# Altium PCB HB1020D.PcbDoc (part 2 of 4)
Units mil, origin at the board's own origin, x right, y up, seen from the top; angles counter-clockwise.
Board outline 4729.44 x 3075.9 mil, 2 copper layers (Top Layer, Bottom Layer); 113 components, 129 nets, 454 pads, 503 vias.
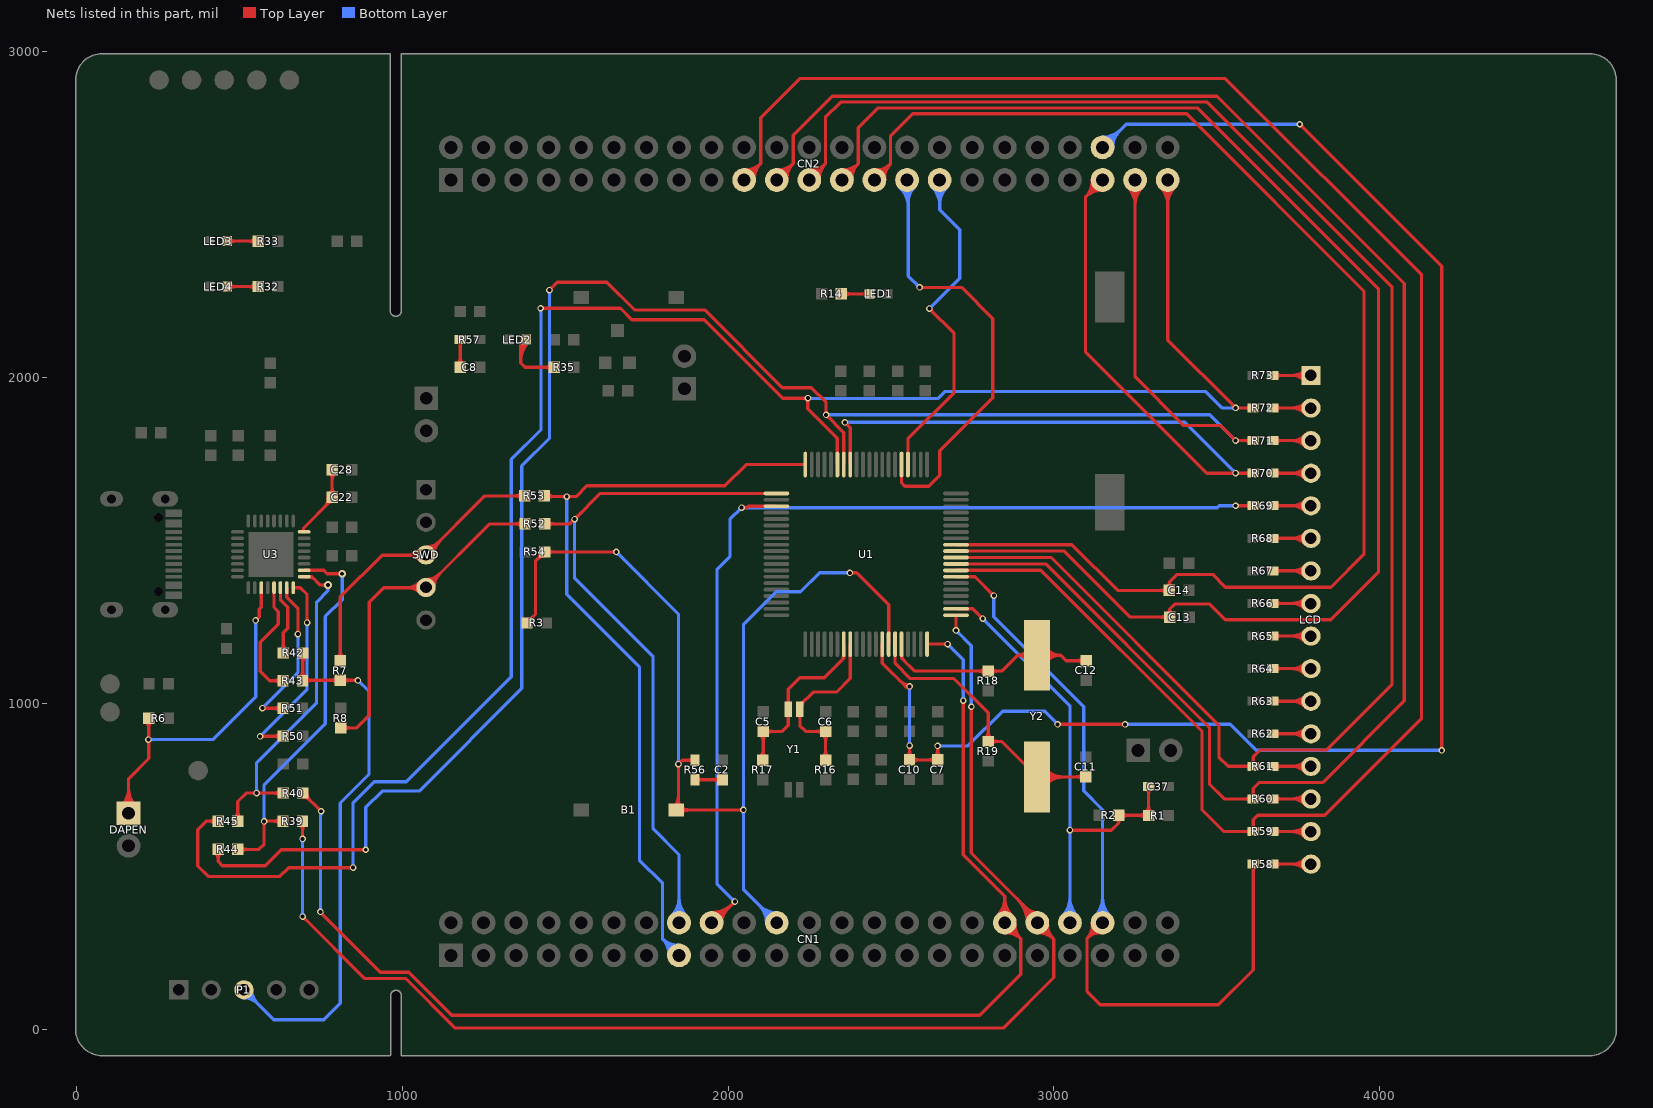
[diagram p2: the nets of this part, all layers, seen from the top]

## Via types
v1: diameter 20, hole 12, Top Layer to Bottom Layer, tented both sides, 475 vias
v2: diameter 23.62, hole 11.81, Top Layer to Bottom Layer, tented both sides, 20 vias
v3: diameter 122.05, hole 122.05, Top Layer to Bottom Layer, tented both sides, 4 vias
v4: diameter 39.37, hole 23.62, Top Layer to Bottom Layer, tented both sides, 2 vias
v5: diameter 30, hole 20, Top Layer to Bottom Layer, tented both sides, 1 vias
v6: diameter 15, hole 8, Top Layer to Bottom Layer, tented both sides, 1 vias

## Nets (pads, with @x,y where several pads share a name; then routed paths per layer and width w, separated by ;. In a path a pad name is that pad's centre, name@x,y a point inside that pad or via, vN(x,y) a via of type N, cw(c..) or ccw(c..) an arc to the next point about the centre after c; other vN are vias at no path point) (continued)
LINK_SWDIO: P1.3 R7.1 R42.2 R43.2 | length 2074.2
  Top Layer w10: R43.2@685.16,1078.84 ccw(c661.41,1102.59) 695,1102.59 ; R42.2@686.16,1146.16 cw(c664.82,1124.82) 695,1124.82 cw(c725.18,1124.82) R42.2@703.84,1146.16 ; R43.2@694,1070 R43.2@695,1071 ; 695,1097.76 ccw(c721.76,1097.76) 702.84,1078.84 ccw(c721.76,1097.76) 721.76,1071 ; R42.2@695,1155 R43.2@695,1071 ; R43.2@702.84,1061.16 cw(c726.59,1037.4) 726.59,1071 ; R7.1@801.16,1062.16 ccw(c779.82,1040.82) 779.82,1071 ccw(c779.83,1101.18) R7.1@801.16,1079.84 ; R7.1@818.84,1062.16 cw(c840.18,1040.82) 840.18,1071 cw(c840.18,1101.18) R7.1@818.84,1079.84 ; v1@860.46,1067.46 ccw(c851.93,1058.93) 851.93,1071 ccw(c851.93,1083.07) v1@860.46,1074.53 ; v1(864,1071) R7.1@810,1071 R43.2@695,1071
  Bottom Layer w10: P1.3@514,96.47 cw(c514,37.26) 555.87,79.13 cw(c597.74,121) P1.3@538.53,121 ; P1.3@514,106.47 cw(c514,71.4) 538.8,96.2 cw(c563.6,121) P1.3@528.53,121 ; P1.3@514,121 606,29 759,29 809.46,79.46 809.46,694.46 898,783 898,1037 v1(864,1071) ; v1@864,1066 cw(c864,1053.93) 872.54,1062.46 cw(c881.07,1071) v1@869,1071
LINK_USART_RX: R39.1 R44.1 U3.26 | length 1393
  Top Layer w10: R44.1@495,552 560,552 576,568 v1(576,638) 577,639 R39.1@634,639 ; R44.1@503.84,543.16 cw(c525.18,521.82) 525.18,552 cw(c525.18,582.18) R44.1@503.84,560.84 ; v1@572.46,634.46 cw(c563.93,625.93) 576,625.93 cw(c588.07,625.93) 579.54,634.46 cw(c590.49,623.51) 590.49,639 ; R39.1@625.16,630.16 ccw(c603.82,608.82) 603.82,639 ccw(c603.82,669.18) R39.1@625.16,647.84 ; U3.26@698.97,1408.57 758.82,1408.57 769.09,1398.31 v2(815.61,1398.31) ; v2@810.79,1393.49 ccw(c799.16,1381.86) 799.16,1398.31 ccw(c799.16,1414.75) v2@810.79,1403.12
  Bottom Layer w10: v1@572.46,641.54 ccw(c563.93,650.07) 576,650.07 ccw(c588.07,650.07) v1@579.54,641.54 ; v1(576,638) 576,750 764.06,938.06 764.06,1267.06 815.61,1318.61 v2(815.61,1398.31) ; v2@810.79,1393.49 cw(c799.16,1381.86) 815.61,1381.86 cw(c832.05,1381.86) v2@820.42,1393.49
LINK_USART_TX: R40.1 R45.1 U3.25 | length 1264.5
  Top Layer w10: R45.1@486.16,647.84 ccw(c464.82,669.18) 495,669.18 ccw(c525.18,669.18) R45.1@503.84,647.84 ; R45.1@495,639 495,699 521,725 v1(553,725) R40.1@635,725 ; v1@549.46,721.46 ccw(c540.93,712.93) 540.93,725 ccw(c540.93,737.07) v1@549.46,728.54 ; v1@556.54,721.46 cw(c565.07,712.93) 565.07,725 cw(c565.07,737.07) v1@556.54,728.54 ; R40.1@626.16,716.16 ccw(c604.82,694.82) 604.82,725 ccw(c604.82,755.18) R40.1@626.16,733.84 ; U3.25@697,1388.89 U3.25@698.97,1388.89 723.02,1388.89 748.61,1363.31 v2(772,1363.31) ; U3.25@713.14,1388.38 cw(c713.14,1363.28) 730.89,1381.03 ; U3.25@713.24,1388.39 cw(c716.47,1372.45) 727.97,1383.95 ; v2@767.18,1358.49 ccw(c755.56,1346.86) 755.56,1363.31 ccw(c755.56,1379.75) v2@767.18,1368.12
  Bottom Layer w10: v1@549.46,728.54 ccw(c540.93,737.07) 553,737.07 ccw(c565.07,737.07) v1@556.54,728.54 ; v1(553,725) 553,818 737,1002 737,1311 772,1346 v2(772,1363.31) ; v2@767.18,1358.49 cw(c755.56,1346.86) 772,1346.86 cw(c788.44,1346.86) v2@776.82,1358.49
LXTAL_IN: C5.2 R17.2 U1.7 Y1.1 | length 753.9
  Top Layer w10: R17.2@2098.16,834.84 ccw(c2074.41,858.59) 2108,858.59 ; C5.2@2099.16,905.16 cw(c2077.82,883.82) 2108,883.82 cw(c2138.18,883.82) 2116.84,905.16 cw(c2138.18,883.82) 2138.18,914 cw(c2138.18,944.18) C5.2@2116.84,922.84 ; R17.2@2107,826 2108,827 C5.2@2108,914 ; C5.2@2107,913 C5.2@2108,914 ; 2108,853.77 ccw(c2134.77,853.77) R17.2@2115.84,834.84 ; Y1.1@2180.45,966.16 cw(c2168.83,954.53) 2185.27,954.53 cw(c2201.71,954.53) Y1.1@2190.08,966.16 ; Y1.1@2180.45,999.42 ccw(c2168.83,1011.04) 2185.27,1011.04 ccw(c2201.71,1011.04) Y1.1@2190.08,999.42 ; 2346.5,1129.5 ccw(c2327.27,1148.73) U1.7@2354.46,1148.73 ; U1.7@2355.37,1182.2 2355.76,1181.81 2355.76,1138.76 2295.5,1078.5 2220.5,1078.5 2185.27,1043.27 Y1.1@2185.27,982.79 2185.27,933.27 2166,914 C5.2@2108,914
LXTAL_OUT: C6.2 R16.2 U1.8 Y1.4 | length 724.9
  Top Layer w10: Y1.4@2215.88,966.16 cw(c2204.26,954.53) 2220.7,954.53 cw(c2237.14,954.53) Y1.4@2225.52,966.16 ; Y1.4@2220.7,1001.41 ccw(c2220.7,1017.61) Y1.4@2232.15,1006.15 ; Y1.4@2227.51,994.6 cw(c2244.2,994.6) Y1.4@2232.4,1006.4 ; R16.2@2290.77,834.84 ccw(c2269.43,856.17) 2299.61,856.17 ; C6.2@2290.77,922.84 cw(c2269.43,944.18) 2269.43,914 cw(c2269.43,883.82) 2290.77,905.16 cw(c2269.43,883.82) 2299.61,883.82 cw(c2329.78,883.82) C6.2@2308.44,905.16 ; R16.2@2299.61,826 C6.2@2299.61,914 2238,914 2220.7,931.3 Y1.4@2220.7,982.79 2220.7,994.7 2261,1035 2333,1035 2375.05,1077.05 U1.8@2375.05,1182.2 ; 2299.61,856.18 ccw(c2329.79,856.18) R16.2@2308.45,834.84
MCU_SWCLK: R8.2 R52.1 SWD.4 | length 1418.3
  Top Layer w10: R8.2@811,925 860,925 899,964 899,1311 943.21,1355.21 SWD.4@1072,1355.21 ; R8.2@819.84,916.16 cw(c841.18,894.82) 841.18,925 cw(c841.18,955.18) R8.2@819.84,933.84 ; 1011.88,1355.21 ccw(c1011.88,1417.12) SWD.4@1055.66,1373.34 ; 1015.69,1355.21 cw(c1015.69,1298.69) SWD.4@1055.66,1338.66 ; 1036.02,1355.21 ccw(c1036.02,1392.98) SWD.4@1062.73,1366.27 ; 1039.83,1355.21 cw(c1039.83,1322.83) SWD.4@1062.73,1345.73 ; SWD.4@1073,1356 1268,1551 R52.1@1377,1551 ; SWD.4@1073,1370.53 ccw(c1073,1405.6) 1097.8,1380.8 ccw(c1122.6,1356) SWD.4@1087.53,1356 ; SWD.4@1073,1380.53 ccw(c1073,1439.74) 1114.87,1397.87 ccw(c1156.74,1356) SWD.4@1097.53,1356 ; R52.1@1368.16,1542.16 ccw(c1346.82,1520.82) 1346.82,1551 ccw(c1346.82,1581.18) R52.1@1368.16,1559.84
MCU_SWDIO: R7.2 R53.1 SWD.3 | length 1280.1
  Top Layer w10: R7.2@801.16,1139.84 ccw(c779.82,1161.18) 810,1161.18 ccw(c840.18,1161.18) R7.2@818.84,1139.84 ; R7.2@810,1131 810,1327 938.21,1455.21 SWD.3@1072,1455.21 ; 1011.88,1455.21 ccw(c1011.88,1517.12) SWD.3@1055.66,1473.34 ; 1015.69,1455.21 cw(c1015.69,1398.69) SWD.3@1055.66,1438.66 ; 1036.02,1455.21 ccw(c1036.02,1492.98) SWD.3@1062.73,1466.27 ; 1039.83,1455.21 cw(c1039.83,1422.83) SWD.3@1062.73,1445.73 ; SWD.3@1073,1456 1254,1637 R53.1@1376,1637 ; SWD.3@1073,1470.53 ccw(c1073,1505.6) 1097.8,1480.8 ccw(c1122.6,1456) SWD.3@1087.53,1456 ; SWD.3@1073,1480.53 ccw(c1073,1539.74) 1114.87,1497.87 ccw(c1156.74,1456) SWD.3@1097.53,1456 ; R53.1@1367.16,1628.16 ccw(c1345.82,1606.82) 1345.82,1637 ccw(c1345.82,1667.18) R53.1@1367.16,1645.84
NetC2_1: C2.1 R56.2 | length 164.7
  Top Layer w10: R56.2@1899,766 C2.1@1983,766 ; R56.2@1905.21,759.79 cw(c1920.2,744.8) 1920.2,766 cw(c1920.2,787.19) R56.2@1905.21,772.21 ; C2.1@1974.16,757.16 ccw(c1952.82,735.82) 1952.82,766 ccw(c1952.82,796.18) C2.1@1974.16,774.84
NetC8_2: C8.2 R57.2 | length 165.7
  Top Layer w10: C8.2@1169.16,2040.84 ccw(c1147.82,2062.18) 1178,2062.18 ccw(c1208.18,2062.18) C8.2@1186.84,2040.84 ; R57.2@1171.79,2110.79 cw(c1156.8,2095.81) 1178,2095.81 cw(c1199.2,2095.81) R57.2@1184.21,2110.79 ; C8.2@1178,2032 R57.2@1178,2117
NetC11_1: C11.1 R19.1 U1.15 Y2.1 | length 1206.2
  Top Layer w10: U1.15@2512.85,1182.2 2512.85,1123.06 2559.61,1076.31 2693.69,1076.31 2798.61,971.39 R19.1@2798.61,883.31 ; R19.1@2789.77,892.15 ccw(c2768.43,913.48) 2798.61,913.48 ccw(c2828.78,913.48) 2807.45,892.15 ccw(c2828.79,913.49) 2828.79,883.31 ccw(c2828.78,853.13) R19.1@2807.45,874.47 ; R19.1@2797.69,883.31 2839.6,883.31 Y2.1@2948.61,774.3 3096.6,774.3 C11.1@3097.61,775.31 ; Y2.1@2965.84,757.07 cw(c3007.44,715.47) 3007.44,774.3 cw(c3007.44,833.13) Y2.1@2965.84,791.53 ; Y2.1@2972.91,750 cw(c3031.58,691.32) 3031.58,774.3 cw(c3031.58,857.28) Y2.1@2972.91,798.6 ; 3065,774.3 ccw(c3065,807.91) C11.1@3088.77,784.14 ; 3069.86,774.3 cw(c3069.86,747.56) C11.1@3088.77,766.47
NetC12_1: C12.1 R18.1 U1.16 Y2.2 | length 1114.1
  Top Layer w10: U1.16@2532.54,1182.2 2532.54,1139.38 2572.61,1099.31 R18.1@2798.61,1099.31 2840.61,1099.31 2889.61,1148.31 ; U1.16@2533.44,1148.73 ccw(c2558.21,1148.73) 2540.7,1131.22 ; R18.1@2789.77,1090.47 ccw(c2768.43,1069.13) 2768.43,1099.31 ccw(c2768.43,1129.49) R18.1@2789.77,1108.15 ; R18.1@2807.45,1090.47 cw(c2828.78,1069.13) 2828.78,1099.31 cw(c2828.79,1129.49) R18.1@2807.45,1108.15 ; Y2.2@2918.71,1131.36 ccw(c2889.61,1114.87) 2889.61,1148.31 ; Y2.2@2918.71,1165.26 cw(c2889.61,1181.76) 2889.61,1148.31 ; Y2.2@2927.41,1136.3 ccw(c2906.78,1124.6) 2906.78,1148.31 ccw(c2906.78,1172.03) Y2.2@2927.41,1160.33 ; Y2.2@2967.53,1132.95 cw(c2999.78,1106.77) 2999.78,1148.31 cw(c2999.78,1189.85) Y2.2@2967.53,1163.67 ; Y2.2@2975.29,1126.65 cw(c3020.78,1089.73) 3020.78,1148.31 ; Y2.2@2975.29,1169.98 ccw(c3020.78,1206.9) 3020.78,1148.31 ; C12.1@3090.77,1122.47 ccw(c3069.43,1101.13) 3069.43,1131.31 ccw(c3069.43,1161.49) C12.1@3090.77,1140.15 ; C12.1@3099.61,1131.31 3037.79,1131.31 3020.78,1148.31 ; 2889.61,1148.31 Y2.2@2948.61,1148.31 3020.78,1148.31
NetC22_2: C22.2 C28.2 U3.32 | length 369.8
  Top Layer w10: U3.32@697,1526.68 697,1538.18 781.11,1622.29 784.61,1625.79 C28.2@784.61,1711.79 ; 697,1532.67 ccw(c704.96,1532.67) U3.32@699.33,1527.05 ; 760.02,1601.21 ccw(c728.44,1632.79) C22.2@773.11,1632.79 ; C22.2@774.51,1615.69 cw(c785.61,1604.6) C22.2@785.61,1620.29 ; C22.2@776.77,1641.63 ccw(c757.84,1660.55) 784.61,1660.55 ; C28.2@776.77,1707.95 cw(c757.84,1689.03) 784.61,1689.03 ; 784.61,1665.38 ccw(c818.2,1665.38) C22.2@794.45,1641.63 ; 784.61,1684.2 cw(c818.2,1684.2) C28.2@794.45,1707.95
NetDAPEN_1: DAPEN.1 R6.1 U3.19 | length 1372.4
  Top Layer w10: DAPEN.1@137.78,685.22 ccw(c84.15,738.85) 160,738.85 ccw(c235.85,738.85) DAPEN.1@182.22,685.22 ; DAPEN.1@144.86,678.14 ccw(c108.29,714.71) 160,714.71 ccw(c211.71,714.71) DAPEN.1@175.14,678.14 ; DAPEN.1@160,663 160,769 222,831 R6.1@222,955 ; R6.1@213.16,946.16 cw(c191.82,924.82) 222,924.82 cw(c252.18,924.82) R6.1@230.84,946.16 ; v1@217.46,885.46 cw(c206.51,874.51) 222,874.51 ; v1@217.46,892.54 ccw(c206.51,903.49) 222,903.49 ; v1(550,1255) 561.19,1266.19 561.19,1289.28 567.08,1295.17 U3.19@567.08,1355.43 ; v1@550,1260 ccw(c550,1272.07) 558.54,1263.54 ccw(c567.07,1255) v1@555,1255
  Bottom Layer w10: v1(221,889) 419,889 550,1020 v1(550,1255) ; v1@224.54,885.46 cw(c233.07,876.93) 233.07,889 cw(c233.07,901.07) v1@224.54,892.54 ; v1@546.46,1251.46 cw(c537.93,1242.93) 550,1242.93 cw(c562.07,1242.93) v1@553.54,1251.46
NetLCD_1: LCD.1 R73.2 | length 298.6
  Top Layer w10: R73.2@3672,2007 LCD.1@3789.2,2007 ; R73.2@3681.93,2000.79 cw(c3696.92,1985.8) 3696.92,2007 cw(c3696.92,2028.2) R73.2@3681.93,2013.21 ; 3729.62,2007 cw(c3729.62,1946.9) LCD.1@3772.11,1989.4 ; 3730.87,2007 ccw(c3730.87,2065.33) LCD.1@3772.11,2024.08 ; 3753.76,2007 cw(c3753.76,1971.04) LCD.1@3779.18,1996.47 ; 3755.01,2007 ccw(c3755.01,2041.19) LCD.1@3779.18,2017.01
NetLCD_2: LCD.2 R72.2 | length 298.6
  Top Layer w10: R72.2@3672,1907 LCD.2@3789.2,1907 ; R72.2@3681.93,1900.79 cw(c3696.92,1885.8) 3696.92,1907 cw(c3696.92,1928.2) R72.2@3681.93,1913.21 ; 3729.62,1907 cw(c3729.62,1846.9) LCD.2@3772.11,1889.4 ; 3730.87,1907 ccw(c3730.87,1965.33) LCD.2@3772.11,1924.08 ; 3753.76,1907 cw(c3753.76,1871.04) LCD.2@3779.18,1896.47 ; 3755.01,1907 ccw(c3755.01,1941.19) LCD.2@3779.18,1917.01
NetLCD_3: LCD.3 R71.2 | length 298.6
  Top Layer w10: R71.2@3672,1807 LCD.3@3789.2,1807 ; R71.2@3681.93,1800.79 cw(c3696.92,1785.8) 3696.92,1807 cw(c3696.92,1828.2) R71.2@3681.93,1813.21 ; 3729.62,1807 cw(c3729.62,1746.9) LCD.3@3772.11,1789.4 ; 3730.87,1807 ccw(c3730.87,1865.33) LCD.3@3772.11,1824.08 ; 3753.76,1807 cw(c3753.76,1771.04) LCD.3@3779.18,1796.47 ; 3755.01,1807 ccw(c3755.01,1841.19) LCD.3@3779.18,1817.01
NetLCD_4: LCD.4 R70.2 | length 298.6
  Top Layer w10: R70.2@3672,1707 LCD.4@3789.2,1707 ; R70.2@3681.93,1700.79 cw(c3696.92,1685.8) 3696.92,1707 cw(c3696.92,1728.2) R70.2@3681.93,1713.21 ; 3729.62,1707 cw(c3729.62,1646.9) LCD.4@3772.11,1689.4 ; 3730.87,1707 ccw(c3730.87,1765.33) LCD.4@3772.11,1724.08 ; 3753.76,1707 cw(c3753.76,1671.04) LCD.4@3779.18,1696.47 ; 3755.01,1707 ccw(c3755.01,1741.19) LCD.4@3779.18,1717.01
NetLCD_5: LCD.5 R69.2 | length 298.6
  Top Layer w10: R69.2@3672,1607 LCD.5@3789.2,1607 ; R69.2@3681.93,1600.79 cw(c3696.92,1585.8) 3696.92,1607 cw(c3696.92,1628.2) R69.2@3681.93,1613.21 ; 3729.62,1607 cw(c3729.62,1546.9) LCD.5@3772.11,1589.4 ; 3730.87,1607 ccw(c3730.87,1665.33) LCD.5@3772.11,1624.08 ; 3753.76,1607 cw(c3753.76,1571.04) LCD.5@3779.18,1596.47 ; 3755.01,1607 ccw(c3755.01,1641.19) LCD.5@3779.18,1617.01
NetLCD_6: LCD.6 R68.2 | length 298.6
  Top Layer w10: R68.2@3672,1507 LCD.6@3789.2,1507 ; R68.2@3681.93,1500.79 cw(c3696.92,1485.8) 3696.92,1507 cw(c3696.92,1528.2) R68.2@3681.93,1513.21 ; 3729.62,1507 cw(c3729.62,1446.9) LCD.6@3772.11,1489.4 ; 3730.87,1507 ccw(c3730.87,1565.33) LCD.6@3772.11,1524.08 ; 3753.76,1507 cw(c3753.76,1471.04) LCD.6@3779.18,1496.47 ; 3755.01,1507 ccw(c3755.01,1541.19) LCD.6@3779.18,1517.01
NetLCD_7: LCD.7 R67.2 | length 298.6
  Top Layer w10: R67.2@3672,1407 LCD.7@3789.2,1407 ; R67.2@3681.93,1400.79 cw(c3696.92,1385.8) 3696.92,1407 cw(c3696.92,1428.2) R67.2@3681.93,1413.21 ; 3729.62,1407 cw(c3729.62,1346.9) LCD.7@3772.11,1389.4 ; 3730.87,1407 ccw(c3730.87,1465.33) LCD.7@3772.11,1424.08 ; 3753.76,1407 cw(c3753.76,1371.04) LCD.7@3779.18,1396.47 ; 3755.01,1407 ccw(c3755.01,1441.19) LCD.7@3779.18,1417.01
NetLCD_8: LCD.8 R66.2 | length 298.6
  Top Layer w10: R66.2@3672,1307 LCD.8@3789.2,1307 ; R66.2@3681.93,1300.79 cw(c3696.92,1285.8) 3696.92,1307 cw(c3696.92,1328.2) R66.2@3681.93,1313.21 ; 3729.62,1307 cw(c3729.62,1246.9) LCD.8@3772.11,1289.4 ; 3730.87,1307 ccw(c3730.87,1365.33) LCD.8@3772.11,1324.08 ; 3753.76,1307 cw(c3753.76,1271.04) LCD.8@3779.18,1296.47 ; 3755.01,1307 ccw(c3755.01,1341.19) LCD.8@3779.18,1317.01
NetLCD_9: LCD.9 R65.2 | length 298.6
  Top Layer w10: R65.2@3672,1207 LCD.9@3789.2,1207 ; R65.2@3681.93,1200.79 cw(c3696.92,1185.8) 3696.92,1207 cw(c3696.92,1228.2) R65.2@3681.93,1213.21 ; 3729.62,1207 cw(c3729.62,1146.9) LCD.9@3772.11,1189.4 ; 3730.87,1207 ccw(c3730.87,1265.33) LCD.9@3772.11,1224.08 ; 3753.76,1207 cw(c3753.76,1171.04) LCD.9@3779.18,1196.47 ; 3755.01,1207 ccw(c3755.01,1241.19) LCD.9@3779.18,1217.01
NetLCD_10: LCD.10 R64.2 | length 298.6
  Top Layer w10: R64.2@3672,1107 LCD.10@3789.2,1107 ; R64.2@3681.93,1100.79 cw(c3696.92,1085.8) 3696.92,1107 cw(c3696.92,1128.2) R64.2@3681.93,1113.21 ; 3729.62,1107 cw(c3729.62,1046.9) LCD.10@3772.11,1089.4 ; 3730.87,1107 ccw(c3730.87,1165.33) LCD.10@3772.11,1124.08 ; 3753.76,1107 cw(c3753.76,1071.04) LCD.10@3779.18,1096.47 ; 3755.01,1107 ccw(c3755.01,1141.19) LCD.10@3779.18,1117.01
NetLCD_11: LCD.11 R63.2 | length 298.6
  Top Layer w10: R63.2@3672,1007 LCD.11@3789.2,1007 ; R63.2@3681.93,1000.79 cw(c3696.92,985.8) 3696.92,1007 cw(c3696.92,1028.2) R63.2@3681.93,1013.21 ; 3729.62,1007 cw(c3729.62,946.9) LCD.11@3772.11,989.4 ; 3730.87,1007 ccw(c3730.87,1065.33) LCD.11@3772.11,1024.08 ; 3753.76,1007 cw(c3753.76,971.04) LCD.11@3779.18,996.47 ; 3755.01,1007 ccw(c3755.01,1041.19) LCD.11@3779.18,1017.01
NetLCD_12: LCD.12 R62.2 | length 298.6
  Top Layer w10: R62.2@3672,907 LCD.12@3789.2,907 ; R62.2@3681.93,900.79 cw(c3696.92,885.8) 3696.92,907 cw(c3696.92,928.2) R62.2@3681.93,913.21 ; 3729.62,907 cw(c3729.62,846.9) LCD.12@3772.11,889.4 ; 3730.87,907 ccw(c3730.87,965.33) LCD.12@3772.11,924.08 ; 3753.76,907 cw(c3753.76,871.04) LCD.12@3779.18,896.47 ; 3755.01,907 ccw(c3755.01,941.19) LCD.12@3779.18,917.01
NetLCD_13: LCD.13 R61.2 | length 298.6
  Top Layer w10: R61.2@3672,807 LCD.13@3789.2,807 ; R61.2@3681.93,800.79 cw(c3696.92,785.8) 3696.92,807 cw(c3696.92,828.2) R61.2@3681.93,813.21 ; 3729.62,807 cw(c3729.62,746.9) LCD.13@3772.11,789.4 ; 3730.87,807 ccw(c3730.87,865.33) LCD.13@3772.11,824.08 ; 3753.76,807 cw(c3753.76,771.04) LCD.13@3779.18,796.47 ; 3755.01,807 ccw(c3755.01,841.19) LCD.13@3779.18,817.01
NetLCD_14: LCD.14 R60.2 | length 298.6
  Top Layer w10: R60.2@3672,707 LCD.14@3789.2,707 ; R60.2@3681.93,700.79 cw(c3696.92,685.8) 3696.92,707 cw(c3696.92,728.2) R60.2@3681.93,713.21 ; 3729.62,707 cw(c3729.62,646.9) LCD.14@3772.11,689.4 ; 3730.87,707 ccw(c3730.87,765.33) LCD.14@3772.11,724.08 ; 3753.76,707 cw(c3753.76,671.04) LCD.14@3779.18,696.47 ; 3755.01,707 ccw(c3755.01,741.19) LCD.14@3779.18,717.01
NetLCD_15: LCD.15 R59.2 | length 298.6
  Top Layer w10: R59.2@3672,607 LCD.15@3789.2,607 ; R59.2@3681.93,600.79 cw(c3696.92,585.8) 3696.92,607 cw(c3696.92,628.2) R59.2@3681.93,613.21 ; 3729.62,607 cw(c3729.62,546.9) LCD.15@3772.11,589.4 ; 3730.87,607 ccw(c3730.87,665.33) LCD.15@3772.11,624.08 ; 3753.76,607 cw(c3753.76,571.04) LCD.15@3779.18,596.47 ; 3755.01,607 ccw(c3755.01,641.19) LCD.15@3779.18,617.01
NetLCD_16: LCD.16 R58.2 | length 298.6
  Top Layer w10: R58.2@3672,507 LCD.16@3789.2,507 ; R58.2@3681.93,500.79 cw(c3696.92,485.8) 3696.92,507 cw(c3696.92,528.2) R58.2@3681.93,513.21 ; 3729.62,507 cw(c3729.62,446.9) LCD.16@3772.11,489.4 ; 3730.87,507 ccw(c3730.87,565.33) LCD.16@3772.11,524.08 ; 3753.76,507 cw(c3753.76,471.04) LCD.16@3779.18,496.47 ; 3755.01,507 ccw(c3755.01,541.19) LCD.16@3779.18,517.01
NetLED1_1: LED1.1 R14.1 | length 172.3
  Top Layer w10: R14.1@2348,2257 LED1.1@2435,2257 ; R14.1@2356.84,2248.16 cw(c2378.18,2226.82) 2378.18,2257 cw(c2378.18,2287.18) R14.1@2356.84,2265.84 ; LED1.1@2427.93,2249.93 ccw(c2410.86,2232.86) 2410.86,2257 ccw(c2410.86,2281.14) LED1.1@2427.93,2264.07
NetLED2_1: LED2.1 R35.1 | length 409.2
  Top Layer w10: 1364.01,2051.84 cw(c1446.16,2051.84) LED2.1@1388.07,2109.93 ; 1364.01,2075.98 cw(c1422.02,2075.98) LED2.1@1381,2117 1364.01,2100.01 ; 1364.01,2100.12 cw(c1397.88,2100.12) LED2.1@1373.93,2124.07 ; LED2.1@1371,2116.97 cw(c1347.13,2116.89) 1364.01,2100.01 ; LED2.1@1380.97,2107 ccw(c1380.89,2083.13) 1364.01,2100.01 ; R35.1@1458.16,2023.16 ccw(c1436.82,2001.82) 1436.82,2032 ccw(c1436.82,2062.18) R35.1@1458.16,2040.84 ; R35.1@1467,2032 1377,2032 1364.01,2044.99 1364.01,2100.01
NetLED3_2: LED3.2 R33.2 | length 181.3
  Top Layer w10: LED3.2@462.61,2419.31 R33.2@558.61,2419.31 ; LED3.2@469.68,2412.24 cw(c486.75,2395.17) 486.75,2419.31 cw(c486.75,2443.45) LED3.2@469.68,2426.38 ; R33.2@549.77,2410.47 ccw(c528.43,2389.13) 528.43,2419.31 ccw(c528.43,2449.49) R33.2@549.77,2428.15
NetLED4_2: LED4.2 R32.2 | length 181.3
  Top Layer w10: LED4.2@462.61,2279.79 R32.2@558.61,2279.79 ; LED4.2@469.68,2272.72 cw(c486.75,2255.65) 486.75,2279.79 cw(c486.75,2303.93) LED4.2@469.68,2286.86 ; R32.2@549.77,2270.95 ccw(c528.43,2249.61) 528.43,2279.79 ccw(c528.43,2309.97) R32.2@549.77,2288.63
NetR42_1: R42.1 U3.22 | length 264.7
  Top Layer w10: U3.22@626.13,1357.39 U3.22@626.13,1355.43 626.13,1318.26 648.61,1295.79 648.61,1230.61 635,1217 R42.1@635,1155 ; R42.1@626.16,1163.84 ccw(c604.82,1185.18) 635,1185.18 ccw(c665.18,1185.18) R42.1@643.84,1163.84
NetR43_1: R43.1 U3.21 | length 416.3
  Top Layer w10: U3.21@606.45,1357.39 U3.21@606.45,1355.43 606.45,1295.03 619.61,1281.88 619.61,1243.61 564,1188 564,1099 593,1070 R43.1@634,1070 ; R43.1@625.16,1061.16 ccw(c603.82,1039.82) 603.82,1070 ccw(c603.82,1100.18) R43.1@625.16,1078.84
NetR50_1: R50.1 U3.24 | length 739.5
  Top Layer w10: v1(564,899) R50.1@634,899 ; v1@567.54,895.46 cw(c576.07,886.93) 576.07,899 cw(c576.07,911.07) v1@567.54,902.54 ; 602.41,899 ccw(c602.41,932.59) R50.1@626.16,908.84 ; 607.24,899 cw(c607.24,872.24) R50.1@626.16,891.16 ; U3.24@665.5,1355.43 686.97,1355.43 708,1334.39 v1(708,1248) ; v1@704.46,1251.54 ccw(c695.93,1260.07) 708,1260.07 ccw(c720.07,1260.07) v1@711.54,1251.54
  Bottom Layer w10: v1(564,899) 708,1043 v1(708,1248) ; v1@564,904 ccw(c564,916.07) 572.54,907.54 ccw(c581.07,899) v1@569,899 ; v1@704.46,1244.46 cw(c695.93,1235.93) 708,1235.93 cw(c720.07,1235.93) v1@711.54,1244.46
NetR51_1: R51.1 U3.23 | length 615.6
  Top Layer w10: v1@571,985 R51.1@634,985 ; v1@574.04,981.96 cw(c581.36,974.64) 581.36,985 ; v1@574.04,989.04 ccw(c583.78,998.78) 583.78,985 ; R51.1@625.16,976.16 ccw(c603.82,954.82) 603.82,985 ccw(c603.82,1015.18) R51.1@625.16,993.84 ; U3.23@645.82,1355.43 645.82,1326.57 679.88,1292.51 v1(679.88,1213.12) ; v1@676.35,1216.65 ccw(c667.81,1225.19) 679.88,1225.19 ccw(c691.95,1225.19) v1@683.42,1216.65
  Bottom Layer w10: v1(570.5,985.5) 679.88,1094.88 v1(679.88,1213.12) ; v1@570.5,990.5 ccw(c570.5,1002.57) 579.04,994.04 ccw(c587.57,985.5) v1@575.5,985.5 ; v1@676.35,1209.58 cw(c667.81,1201.05) 679.88,1201.05 cw(c691.95,1201.05) v1@683.42,1209.58
NRST: B1.2 CN1.22 R3.2 R54.2 R56.1 U1.14 | length 3906.1
  Top Layer w10: R3.2@1383,1247 1409,1273 1409,1437 R54.2@1437,1465 v1(1657,1465) ; R3.2@1383,1259.5 ccw(c1383,1289.68) 1404.34,1268.34 ccw(c1425.68,1247) R3.2@1395.5,1247 ; R54.2@1424.5,1465 cw(c1394.32,1465) 1415.66,1443.66 cw(c1437,1422.32) R54.2@1437,1452.5 ; R54.2@1445.84,1456.16 cw(c1467.18,1434.82) 1467.18,1465 cw(c1467.18,1495.18) R54.2@1445.84,1473.84 ; v1@1653.46,1461.46 ccw(c1644.93,1452.93) 1644.93,1465 ccw(c1644.93,1477.07) v1@1653.46,1468.54 ; B1.2@1834.5,683.38 ccw(c1801.9,715.98) 1848,715.98 ; v1@1844.46,810.46 cw(c1835.93,801.93) 1848,801.93 cw(c1860.07,801.93) v1@1851.54,810.46 ; 1848,700.93 ccw(c1872.81,700.93) 1855.27,683.38 ccw(c1880.34,708.45) 1880.34,673 ccw(c1880.34,637.55) B1.2@1855.27,662.62 ; v1@1848,819 ccw(c1848,831.07) 1856.54,822.54 ccw(c1865.07,814) v1@1853,814 ; R56.1@1892.79,819.79 ccw(c1877.8,804.8) 1877.8,826 ccw(c1877.8,847.19) R56.1@1892.79,832.21 ; R56.1@1899,826 1860,826 v1(1848,814) 1848,680.05 B1.2@1840.95,673 v1(2047.3,673) ; v1@2043.76,669.46 ccw(c2035.23,660.93) 2035.23,673 ccw(c2035.23,685.07) v1@2043.76,676.54 ; v1(2374,1401) 2394.53,1401 2493.17,1302.36 U1.14@2493.17,1182.2 ; v1@2377.54,1397.46 cw(c2386.07,1388.93) 2386.07,1401 cw(c2386.07,1413.07) v1@2377.54,1404.54
  Bottom Layer w10: v1@1657,1460 cw(c1657,1447.93) 1665.54,1456.46 cw(c1674.07,1465) v1@1662,1465 ; v1(1657,1465) 1848,1274 v1(1848,814) ; v1@1844.46,817.54 ccw(c1835.93,826.07) 1848,826.07 ccw(c1860.07,826.07) v1@1851.54,817.54 ; v1@2043.76,669.46 cw(c2035.23,660.93) 2047.3,660.93 cw(c2059.37,660.93) v1@2050.83,669.46 ; v1@2043.76,676.54 ccw(c2035.23,685.07) 2047.3,685.07 ccw(c2059.37,685.07) v1@2050.83,676.54 ; CN1.22@2118.19,326.79 ccw(c2042.34,326.79) 2095.97,380.42 ccw(c2149.61,434.05) CN1.22@2149.61,358.21 ; CN1.22@2128.19,326.79 ccw(c2076.48,326.79) 2113.04,363.35 ccw(c2149.61,399.91) CN1.22@2149.61,348.21 ; CN1.22@2148.61,324.62 CN1.22@2148.61,326.79 ; CN1.22@2149.61,326.79 2047.3,429.1 2047.3,1242.08 2147.79,1342.57 2222.57,1342.57 2281,1401 v1(2374,1401) ; v1@2370.46,1397.46 ccw(c2361.93,1388.93) 2361.93,1401 ccw(c2361.93,1413.07) v1@2370.46,1404.54
PA0: C7.2 C10.2 CN2.42 U1.13 | length 5608.1
  Top Layer w10: U1.13@2473.48,1182.2 2473.48,1123.52 2545,1052 ; 2527.33,1069.67 ccw(c2557.27,1099.61) v1@2557.27,1057.27 ; 2544.4,1052.6 ccw(c2557.27,1065.47) v1@2557.27,1047.27 ; 2545.85,1052 cw(c2545.85,1040.85) v1@2553.73,1048.73 ; C10.2@2548.43,835.62 ccw(c2527.09,856.96) 2557.27,856.96 ccw(c2587.45,856.96) 2566.11,835.62 ccw(c2587.45,856.96) 2587.45,826.79 ccw(c2587.45,796.61) C10.2@2566.11,817.95 ; v1@2553.64,1055.71 cw(c2545,1063.92) 2545,1052 ; v1@2553.73,867.19 cw(c2545.2,858.66) 2557.27,858.66 cw(c2569.34,858.66) v1@2560.81,867.19 ; v1(2557.27,870.73) C10.2@2557.27,826.79 C7.2@2643.61,826.79 v1(2643.61,869.61) ; v1(2557.27,1052.27) 2557.27,1052.05 2557.22,1052 2545,1052 ; C7.2@2634.77,817.95 ccw(c2613.43,796.61) 2613.43,826.79 ccw(c2613.43,856.96) 2634.77,835.62 ccw(c2613.43,856.96) 2643.61,856.96 ccw(c2673.79,856.97) C7.2@2652.45,835.62 ; v1@2640.07,866.07 cw(c2631.53,857.53) 2643.61,857.53 cw(c2655.68,857.53) v1@2647.14,866.07 ; v1(3012,936) v1(3219,936) ; v1@3015.54,932.46 cw(c3024.07,923.93) 3024.07,936 cw(c3024.07,948.07) v1@3015.54,939.54 ; v1@3215.46,932.46 ccw(c3206.93,923.93) 3206.93,936 ccw(c3206.93,948.07) v1@3215.46,939.54 ; v1@3755,2773 cw(c3755,2760.93) 3763.54,2769.46 cw(c3772.07,2778) v1@3760,2778 ; v1(3755,2778) 4191,2342 v1(4191,856) ; v1@4187.46,859.54 ccw(c4178.93,868.07) 4191,868.07 ccw(c4203.07,868.07) v1@4194.54,859.54
  Bottom Layer w10: v1@2553.73,874.27 ccw(c2545.2,882.8) 2557.27,882.8 ccw(c2569.34,882.8) v1@2560.81,874.27 ; v1@2553.73,1048.73 cw(c2545.2,1040.2) 2557.27,1040.2 cw(c2569.34,1040.2) v1@2560.81,1048.73 ; v1(2557.27,870.73) v1(2557.27,1052.27) ; v1(2643.61,869.61) 2736.61,869.61 2843,976 2972,976 v1(3012,936) ; v1@2647.14,866.07 cw(c2655.68,857.53) 2655.68,869.61 cw(c2655.68,881.68) v1@2647.14,873.14 ; v1@3007,936 ccw(c2994.93,936) 3003.46,944.54 ccw(c3012,953.07) v1@3012,941 ; CN2.42@3149.61,2706.79 3150.77,2706.79 3221.98,2778 v1(3755,2778) ; CN2.42@3149.61,2728.21 ccw(c3149.61,2782.73) 3188.16,2744.17 ; CN2.42@3149.61,2738.21 ccw(c3149.61,2816.87) 3205.23,2761.25 ; CN2.42@3171.02,2706.79 cw(c3219.91,2706.79) 3185.34,2741.36 ; CN2.42@3181.02,2706.79 cw(c3254.06,2706.79) 3202.41,2758.43 ; v1(3219,936) 3541,936 3621,856 v1(4191,856) ; v1@3222.54,932.46 cw(c3231.07,923.93) 3231.07,936 cw(c3231.07,948.07) v1@3222.54,939.54 ; v1@3751.46,2774.46 ccw(c3742.93,2765.93) 3742.93,2778 ccw(c3742.93,2790.07) v1@3751.46,2781.54 ; v1@4187.46,852.46 ccw(c4178.93,843.93) 4178.93,856 ccw(c4178.93,868.07) v1@4187.46,859.54
PA1: CN1.36 R40.2 U1.20 | length 4450.9
  Top Layer w10: R40.2@695,712.5 cw(c695,682.32) 716.34,703.66 cw(c737.68,725) R40.2@707.5,725 ; R40.2@695,725 v1(751,669) ; v1@746,669 ccw(c733.93,669) 742.46,677.53 ccw(c751,686.07) v1@751,674 ; v1@751,356 932,175 1020,175 1152,43 2773,43 2899,169 2899,277.39 ; v1@753.99,360 ccw(c770.86,360) 758.93,348.07 ; U1.20@2611.28,1182.2 v1(2674,1182.2) ; v1@2670.46,1178.66 ccw(c2661.93,1170.12) 2661.93,1182.2 ccw(c2661.93,1194.27) v1@2670.46,1185.73 ; v1@2718.46,1005.46 cw(c2709.93,996.93) 2722,996.93 cw(c2734.07,996.93) v1@2725.54,1005.46 ; v1(2722,1009) 2722,535.65 2849.61,408.04 CN1.36@2849.61,326.79 2899,277.39 ; CN1.36@2827.39,349 ccw(c2773.76,402.64) 2849.61,402.64 ccw(c2925.45,402.64) CN1.36@2871.82,349 ; CN1.36@2834.46,341.93 ccw(c2797.9,378.49) 2849.61,378.49 ccw(c2901.31,378.49) CN1.36@2864.75,341.93 ; CN1.36@2850.89,305.41 cw(c2853.42,263.26) 2883.28,293.12 cw(c2913.13,322.97) CN1.36@2870.99,325.5 ; CN1.36@2851.49,295.43 cw(c2855.2,233.6) 2899,277.4 ; CN1.36@2880.97,324.91 ccw(c2942.8,321.19) 2899,277.4
  Bottom Layer w10: v1@745.45,363.54 ccw(c736.92,372.07) 748.99,372.07 ccw(c761.06,372.07) v1@752.52,363.54 ; v1(748.99,360) v1@748.99,666.99 ; 748.99,652.07 cw(c767.93,652.07) v1@754.54,665.46 ; v1@2674,1177.2 cw(c2674,1165.12) 2682.54,1173.66 cw(c2691.07,1182.2) v1@2679,1182.2 ; v1(2674,1182.2) 2722,1134.2 v1(2722,1009) ; v1@2718.46,1012.54 ccw(c2709.93,1021.07) 2722,1021.07 ccw(c2734.07,1021.07) v1@2725.54,1012.54
PA2: CN1.38 R39.2 U1.21 | length 4647.8
  Top Layer w10: R39.2@685.16,630.16 cw(c663.82,608.82) 694,608.82 cw(c724.18,608.82) R39.2@702.84,630.16 ; v1@690.46,587.54 ccw(c681.93,596.07) 694,596.07 ccw(c706.07,596.07) v1@697.53,587.54 ; v1@694,341 cw(c694,328.93) 702.53,337.47 cw(c711.07,346) v1@699,346 ; v1(694,346) 884,156 1010,156 1162.39,3.61 2844.77,3.61 3000,158.84 3000,276.39 ; v1(694,584) R39.2@694,639 ; v1@2696.32,1227.68 ccw(c2687.79,1236.21) 2699.86,1236.21 ccw(c2711.93,1236.21) v1@2703.39,1227.68 ; v1(2699.86,1224.14) U1.21@2699.86,1270.78 ; v1@2743.46,986.46 cw(c2734.93,977.93) 2747,977.93 cw(c2759.07,977.93) v1@2750.54,986.46 ; v1(2747,990) 2747,541 2949.61,338.39 CN1.38@2949.61,326.79 3000,276.39 ; 2887.77,400.23 cw(c2814.32,326.79) CN1.38@2918.19,326.79 ; 2904.84,383.16 cw(c2848.46,326.79) CN1.38@2928.19,326.79 ; 2915.79,372.21 ccw(c2949.61,406.03) CN1.38@2949.61,358.21 ; 2921.91,366.09 cw(c2882.61,326.79) CN1.38@2938.19,326.79 ; CN1.38@2950.57,305.39 cw(c2952.57,261.05) 2983.96,292.44 cw(c3015.35,323.82) CN1.38@2971,325.82 ; CN1.38@2951.02,295.4 cw(c2953.95,230.35) 3000,276.4 ; CN1.38@2980.99,325.37 ccw(c3046.04,322.44) 3000,276.4
  Bottom Layer w10: v1@690.46,349.54 ccw(c681.93,358.07) 694,358.07 ccw(c706.07,358.07) v1@697.53,349.54 ; v1@690.46,580.47 cw(c681.93,571.93) 694,571.93 cw(c706.07,571.93) v1@697.53,580.47 ; v1(694,346) v1(694,584) ; v1@2699.86,1219.14 cw(c2699.86,1207.07) 2708.39,1215.61 cw(c2716.93,1224.14) v1@2704.86,1224.14 ; v1(2699.86,1224.14) 2747,1177 v1(2747,990) ; v1@2743.46,993.54 ccw(c2734.93,1002.07) 2747,1002.07 ccw(c2759.07,1002.07) v1@2750.54,993.54
PA3: C37.1 CN1.40 R1.1 R2.2 U1.22 | length 2005.8
  Top Layer w10: U1.22@2699.86,1290.46 2751.73,1290.46 v1(2782,1260.2) ; v1@2777,1260.2 ccw(c2764.93,1260.2) 2773.46,1268.73 ccw(c2782,1277.27) v1@2782,1265.2 ; v1(3049.61,611) 3177,611 3199,633 ; v1@3053.14,607.46 cw(c3061.68,598.93) 3061.68,611 cw(c3061.68,623.07) v1@3053.14,614.54 ; R2.2@3191.83,646.76 cw(c3182.21,633) 3199,633 ; R2.2@3206.17,646.76 ccw(c3215.79,633) 3199,633 ; R2.2@3207.84,648.16 cw(c3229.18,626.82) 3229.18,657 cw(c3229.18,687.18) R2.2@3207.84,665.84 ; 3258.41,657 cw(c3258.41,623.41) R1.1@3282.16,647.16 ; 3263.24,657 ccw(c3263.24,683.76) 3282.16,664.84 ccw(c3260.82,686.18) 3291,686.18 ccw(c3321.18,686.18) R1.1@3299.84,664.84 ; C37.1@3284.79,738.79 cw(c3269.8,723.8) 3291,723.8 cw(c3312.2,723.8) C37.1@3297.21,738.79 ; C37.1@3291,745 R1.1@3291,656 3290,657 R2.2@3199,657 3199,633
  Bottom Layer w10: v1@2782,1255.2 cw(c2782,1243.12) 2790.54,1251.66 cw(c2799.07,1260.2) v1@2787,1260.2 ; v1(2782,1260.2) 3049.61,992.59 v1(3049.61,611) CN1.40@3049.61,326.79 ; CN1.40@3027.39,349 ccw(c2973.76,402.64) 3049.61,402.64 ccw(c3125.45,402.64) CN1.40@3071.82,349 ; CN1.40@3034.46,341.93 ccw(c2997.9,378.49) 3049.61,378.49 ccw(c3101.31,378.49) CN1.40@3064.75,341.93 ; v1@3046.07,607.46 cw(c3037.54,598.93) 3049.61,598.93 cw(c3061.68,598.93) v1@3053.14,607.46 ; v1@3046.07,614.54 ccw(c3037.54,623.07) 3049.61,623.07 ccw(c3061.68,623.07) v1@3053.14,614.54
PA4: CN1.42 R58.1 U1.27 | length 2845.8
  Top Layer w10: U1.27@2699.86,1388.89 2758.11,1388.89 v1(2816,1331) ; v1@2811,1331 ccw(c2798.93,1331) 2807.46,1339.54 ccw(c2816,1348.07) v1@2816,1336 ; CN1.42@3118.32,323.94 cw(c3062.7,318.87) 3102.19,279.37 ; CN1.42@3128.28,324.84 cw(c3090.36,321.39) 3117.28,294.46 cw(c3144.21,267.54) CN1.42@3147.66,305.46 ; CN1.42@3146.75,295.5 ccw(c3141.68,239.88) 3102.19,279.37 ; CN1.42@3149.61,326.79 3102.19,279.37 ; R58.1@3605.79,500.79 cw(c3590.8,485.8) 3612,485.8 cw(c3633.2,485.8) R58.1@3618.21,500.79 ; R58.1@3612,507 3612,181.79 3505.02,74.81 3143,74.81 3102.19,115.62 3102.19,279.37
  Bottom Layer w10: v1@2812.46,1327.46 cw(c2803.93,1318.93) 2816,1318.93 cw(c2828.07,1318.93) v1@2819.54,1327.46 ; v1(2816,1331) 2816,1266.51 3092,990.51 3092,732 3149.61,674.39 3149.61,607 CN1.42@3149.61,326.79 ; CN1.42@3127.39,349 ccw(c3073.76,402.64) 3149.61,402.64 ccw(c3225.45,402.64) CN1.42@3171.82,349 ; CN1.42@3134.46,341.93 ccw(c3097.9,378.49) 3149.61,378.49 ccw(c3201.31,378.49) CN1.42@3164.75,341.93
PA5: CN2.19 R59.1 U1.28 | length 6218.3
  Top Layer w10: CN2.19@2049.61,2606.79 2100.19,2657.37 ; CN2.19@2050.51,2628.19 ccw(c2052.41,2672.95) 2084.09,2641.27 ccw(c2115.77,2609.59) CN2.19@2071,2607.69 ; CN2.19@2050.94,2638.18 ccw(c2053.71,2703.84) 2100.19,2657.37 ; CN2.19@2081,2608.12 cw(c2146.66,2610.9) 2100.19,2657.37 ; U1.28@2699.86,1408.57 2960.43,1408.57 3455,914 3455,674 3522,607 R59.1@3612,607 3612,643 3626,657 3832,657 4129,954 4129,2316 3527,2918 2219.87,2918 2100.19,2798.32 2100.19,2657.37 ; R59.1@3602.07,600.79 ccw(c3587.08,585.8) 3587.08,607 ccw(c3587.08,628.2) R59.1@3602.07,613.21 ; R59.1@3605.79,613.21 ccw(c3590.8,628.2) 3612,628.2 ccw(c3633.2,628.2) R59.1@3618.21,613.21
PA6: CN2.21 R60.1 U1.29 | length 5772.7
  Top Layer w10: CN2.21@2149.61,2606.79 2200.19,2657.37 ; CN2.21@2150.51,2628.19 ccw(c2152.41,2672.95) 2184.09,2641.27 ccw(c2215.77,2609.59) CN2.21@2171,2607.69 ; CN2.21@2150.94,2638.18 ccw(c2153.71,2703.84) 2200.19,2657.37 ; CN2.21@2181,2608.12 cw(c2246.66,2610.9) 2200.19,2657.37 ; U1.29@2699.86,1428.26 2975.74,1428.26 3478,926 3478,752 3523,707 R60.1@3612,707 3612,739 3630,757 3825,757 4076,1008 4076,2289 3501,2864 2320.12,2864 2200.19,2744.07 2200.19,2657.37 ; R60.1@3602.07,700.79 ccw(c3587.08,685.8) 3587.08,707 ccw(c3587.08,728.2) R60.1@3602.07,713.21 ; R60.1@3605.79,713.21 ccw(c3590.8,728.2) 3612,728.2 ccw(c3633.2,728.2) R60.1@3618.21,713.21
PA7: CN2.23 R61.1 U1.30 | length 5452.4
  Top Layer w10: CN2.23@2249.61,2606.79 2299.02,2656.2 ; CN2.23@2250.88,2628.17 ccw(c2253.4,2670.37) 2283.29,2640.47 ccw(c2313.18,2610.58) CN2.23@2270.99,2608.06 ; CN2.23@2251.48,2638.15 ccw(c2255.17,2700.05) 2299.02,2656.2 ; CN2.23@2280.97,2608.66 cw(c2342.87,2612.35) 2299.02,2656.2 ; U1.30@2699.86,1447.94 2992.06,1447.94 3507,933 3507,835 3535,807 R61.1@3612,807 3612,836 3633,857 3837,857 4038,1058 4038,2279.54 3471.54,2846 2345.52,2846 2299.02,2799.51 2299.02,2656.2 ; R61.1@3602.07,800.79 ccw(c3587.08,785.8) 3587.08,807 ccw(c3587.08,828.2) R61.1@3602.07,813.21 ; R61.1@3605.79,813.21 ccw(c3590.8,828.2) 3612,828.2 ccw(c3633.2,828.2) R61.1@3618.21,813.21
PA8: CN2.31 U1.44 | length 1266.1
  Top Layer w10: U1.44@2552.22,1733.38 2552.22,1812.22 2694,1954 2694,2136 v1(2618,2212) ; v1@2618,2207 cw(c2618,2194.93) 2626.54,2203.46 cw(c2635.07,2212) v1@2623,2212
  Bottom Layer w10: v1(2618,2212) 2711.25,2305.25 2711.25,2453.75 2649.61,2515.39 CN2.31@2649.61,2606.79 ; v1@2618,2217 ccw(c2618,2229.07) 2626.54,2220.54 ccw(c2635.07,2212) v1@2623,2212 ; CN2.31@2627.39,2584.57 cw(c2573.76,2530.94) 2649.61,2530.94 cw(c2725.45,2530.94) CN2.31@2671.82,2584.57 ; CN2.31@2634.46,2591.64 cw(c2597.9,2555.08) 2649.61,2555.08 cw(c2701.31,2555.08) CN2.31@2664.75,2591.64
PA9: CN2.29 U1.45 | length 1584.6
  Top Layer w10: U1.45@2532.54,1733.38 2532.54,1676.91 2543,1666.45 2616.45,1666.45 2650,1700 2650,1775 2813,1938 2813,2181 2717,2277 v1(2588,2277) ; v1@2591.54,2273.46 cw(c2600.07,2264.93) 2600.07,2277 cw(c2600.07,2289.07) v1@2591.54,2280.54
  Bottom Layer w10: CN2.29@2527.39,2584.57 cw(c2465.56,2522.75) 2553,2522.75 ; CN2.29@2534.46,2591.64 cw(c2489.71,2546.89) 2553,2546.89 ; 2553,2539.13 cw(c2617.26,2539.13) CN2.29@2571.82,2584.57 ; 2553,2563.28 cw(c2593.12,2563.28) CN2.29@2564.75,2591.64 ; CN2.29@2553,2603.39 2553,2312 v1(2588,2277) ; v1@2583,2277 ccw(c2570.93,2277) 2579.46,2285.54 ccw(c2588,2294.07) v1@2588,2282
PA10: CN2.41 R70.1 U1.53 | length 2940.6
  Top Layer w10: v1@2359,1858 cw(c2359,1845.93) 2367.54,1854.46 cw(c2376.07,1863) v1@2364,1863 ; v1(2359,1863) 2375.05,1846.94 U1.53@2375.05,1733.38 ; CN2.41@3118.19,2606.35 cw(c3045.83,2605.36) 3097,2554.19 ; CN2.41@3128.19,2606.49 cw(c3078.86,2605.81) 3113.75,2570.93 cw(c3148.63,2536.05) CN2.41@3149.31,2585.37 ; CN2.41@3149.17,2575.37 ccw(c3148.17,2503.02) 3097,2554.19 ; CN2.41@3149.61,2606.79 3097,2554.18 ; v1@3554.46,1703.46 ccw(c3545.93,1694.93) 3545.93,1707 ccw(c3545.93,1719.07) v1@3554.46,1710.54 ; v1@3561.54,1703.46 cw(c3570.07,1694.93) 3570.07,1707 cw(c3570.07,1719.07) v1@3561.54,1710.54 ; R70.1@3602.07,1700.79 ccw(c3587.08,1685.8) 3587.08,1707 ccw(c3587.08,1728.2) R70.1@3602.07,1713.21 ; R70.1@3612,1707 v1(3558,1707) 3470,1707 3097,2080 3097,2554.18
  Bottom Layer w10: v1(2359,1863) 3402,1863 v1(3558,1707) ; v1@2362.54,1859.46 cw(c2371.07,1850.93) 2371.07,1863 cw(c2371.07,1875.07) v1@2362.54,1866.54 ; v1@3553,1707 ccw(c3540.93,1707) 3549.46,1715.54 ccw(c3558,1724.07) v1@3558,1712
PA11: CN2.43 R44.2 R71.1 U1.54 | length 6567.1
  Top Layer w10: R44.2@426.16,543.16 cw(c404.82,521.82) 435,521.82 cw(c465.18,521.82) R44.2@443.84,543.16 ; R44.2@435,552 435,515 448,502 579,502 628,551 v1(888,551) ; v1@884.46,547.46 ccw(c875.93,538.93) 875.93,551 ccw(c875.93,563.07) v1@884.46,554.54 ; v1(1452,2269) 1476,2293 1628,2293 1713,2208 1928,2208 2167,1969 2256,1969 2301,1924 v1(2301,1886) 2355.37,1831.63 U1.54@2355.37,1733.38 ; v1@1452,2274 ccw(c1452,2286.07) 1460.54,2277.54 ccw(c1469.07,2269) v1@1457,2269 ; v1@2297.46,1889.54 ccw(c2288.93,1898.07) 2301,1898.07 ccw(c2313.07,1898.07) v1@2304.54,1889.54 ; v1@2301,1881 cw(c2301,1868.93) 2309.54,1877.46 cw(c2318.07,1886) v1@2306,1886 ; CN2.43@3227.39,2584.57 cw(c3173.76,2530.94) 3249.61,2530.94 cw(c3325.45,2530.94) CN2.43@3271.82,2584.57 ; CN2.43@3234.46,2591.64 cw(c3197.9,2555.08) 3249.61,2555.08 cw(c3301.31,2555.08) CN2.43@3264.75,2591.64 ; CN2.43@3249.61,2606.79 3249.61,2002.39 3399,1853 3512,1853 v1(3558,1807) R71.1@3612,1807 ; v1@3553,1807 ccw(c3540.93,1807) 3549.46,1815.54 ccw(c3558,1824.07) v1@3558,1812 ; v1@3561.54,1803.46 cw(c3570.07,1794.93) 3570.07,1807 cw(c3570.07,1819.07) v1@3561.54,1810.54 ; R71.1@3602.07,1800.79 ccw(c3587.08,1785.8) 3587.08,1807 ccw(c3587.08,1828.2) R71.1@3602.07,1813.21
  Bottom Layer w10: v1@884.46,554.54 ccw(c875.93,563.07) 888,563.07 ccw(c900.07,563.07) v1@891.54,554.54 ; v1(888,551) 888,681 938,731 1052,731 1367,1046 1367,1729 1452,1814 v1(1452,2269) ; v1@1448.46,2265.46 cw(c1439.93,2256.93) 1452,2256.93 cw(c1464.07,2256.93) v1@1455.54,2265.46 ; v1(2301,1886) 3479,1886 v1(3558,1807) ; v1@2304.54,1882.46 cw(c2313.07,1873.93) 2313.07,1886 cw(c2313.07,1898.07) v1@2304.54,1889.54 ; v1@3553,1807 ccw(c3540.93,1807) 3549.46,1815.54 ccw(c3558,1824.07) v1@3558,1812
PA12: CN2.45 R45.2 R72.1 U1.55 | length 6524.6
  Top Layer w10: R45.2@426.16,630.16 ccw(c404.82,608.82) 404.82,639 ccw(c404.82,669.18) R45.2@426.16,647.84 ; R45.2@435,639 398,639 372,613 372,501 404,469 624,469 651,496 v1(849,496) ; v1@845.46,492.46 ccw(c836.93,483.93) 836.93,496 ccw(c836.93,508.07) v1@845.46,499.54 ; v1(1424.93,2212.99) 1670.01,2212.99 1705,2178 1927,2178 2168,1937 v1(2245,1937) 2245,1905 2335.68,1814.32 U1.55@2335.68,1733.38 ; v1@1428.46,2209.46 cw(c1437,2200.92) 1437,2212.99 cw(c1437,2225.06) v1@1428.46,2216.53 ; v1@2241.46,1940.54 cw(c2232.93,1949.07) 2232.93,1937 cw(c2232.93,1924.93) 2241.46,1933.46 cw(c2232.93,1924.93) 2245,1924.93 cw(c2257.07,1924.93) v1@2248.54,1933.46 ; CN2.45@3327.39,2584.57 cw(c3273.76,2530.94) 3349.61,2530.94 cw(c3425.45,2530.94) CN2.45@3371.82,2584.57 ; CN2.45@3334.46,2591.64 cw(c3297.9,2555.08) 3349.61,2555.08 cw(c3401.31,2555.08) CN2.45@3364.75,2591.64 ; CN2.45@3349.61,2606.79 3349.61,2115.39 v1(3558,1907) R72.1@3612,1907 ; v1@3553,1907 ccw(c3540.93,1907) 3549.46,1915.54 ccw(c3558,1924.07) v1@3558,1912 ; v1@3561.54,1903.46 cw(c3570.07,1894.93) 3570.07,1907 cw(c3570.07,1919.07) v1@3561.54,1910.54 ; R72.1@3602.07,1900.79 ccw(c3587.08,1885.8) 3587.08,1907 ccw(c3587.08,1928.2) R72.1@3602.07,1913.21
  Bottom Layer w10: v1@845.46,499.54 ccw(c836.93,508.07) 849,508.07 ccw(c861.07,508.07) v1@852.54,499.54 ; v1(849,496) 849,695 914,760 1013,760 1335,1082 1335,1749 1426,1840 1426,2211.92 v1(1424.93,2212.99) ; v1@1421.39,2209.46 cw(c1410.26,2198.33) 1426,2198.33 ; v1(2245,1937) 2245.71,1936.29 2645.29,1936.29 2666.79,1957.79 3465.21,1957.79 3516,1907 v1(3558,1907) ; v1@2248.54,1933.46 cw(c2255.35,1926.65) 2255.35,1936.29 ; v1@2248.54,1940.54 ccw(c2258.8,1950.79) 2258.8,1936.29 ; v1@3554.46,1903.46 ccw(c3545.93,1894.93) 3545.93,1907 ccw(c3545.93,1919.07) v1@3554.46,1910.54
PA13: CN1.15 R53.2 U1.60 | length 2675.2
  Top Layer w10: R53.2@1438,1635 v1(1505,1635) ; R53.2@1444.84,1628.16 cw(c1461.35,1611.65) 1461.35,1635 ; R53.2@1444.84,1645.84 ccw(c1471.01,1672.01) 1471.01,1635 ; v1@1501.46,1631.46 ccw(c1492.93,1622.93) 1492.93,1635 ccw(c1492.93,1647.07) v1@1501.46,1638.54 ; v1@1508,1635 1534,1635 1567,1668 1990.53,1668 2055.91,1733.38 U1.60@2237.26,1733.38 ; v1@1508.54,1631.46 cw(c1517.07,1622.93) 1517.07,1635 cw(c1517.07,1647.07) v1@1508.54,1638.54
  Bottom Layer w10: v1@1501.46,1631.46 cw(c1492.93,1622.93) 1505,1622.93 cw(c1517.07,1622.93) v1@1508.54,1631.46 ; v1(1505,1635) 1505,1335 1728,1112 1728,519 1799.02,447.98 1799.02,277.37 ; CN1.15@1818.22,228.12 ccw(c1752.56,230.9) 1799.03,277.37 ; CN1.15@1828.21,227.69 ccw(c1783.45,229.59) 1815.13,261.27 ccw(c1846.81,292.95) CN1.15@1848.7,248.19 ; CN1.15@1848.28,258.18 cw(c1845.5,323.84) 1799.03,277.37 ; CN1.15@1849.61,226.79 1799.02,277.37
PA14: CN1.16 R52.2 U1.61 | length 2427.2
  Top Layer w10: R52.2@1437,1551 1513.95,1551 v1(1528.95,1566) 1607.74,1644.8 U1.61@2148.68,1644.8 ; R52.2@1445.84,1542.16 cw(c1467.18,1520.82) 1467.18,1551 cw(c1467.18,1581.18) R52.2@1445.84,1559.84 ; v1@1523.95,1566 cw(c1511.88,1566) 1520.41,1557.46 cw(c1528.95,1548.93) v1@1528.95,1561 ; v1@1528.95,1571 ccw(c1528.95,1583.07) 1537.48,1574.54 ccw(c1546.02,1566) v1@1533.95,1566
  Bottom Layer w10: v1@1525.41,1562.46 cw(c1516.88,1553.93) 1528.95,1553.93 cw(c1541.02,1553.93) v1@1532.48,1562.46 ; v1(1528.95,1566) 1528.95,1384.05 1770,1143 1770,615 1849.61,535.39 CN1.16@1849.61,326.79 ; CN1.16@1827.39,349 ccw(c1773.76,402.64) 1849.61,402.64 ccw(c1925.45,402.64) CN1.16@1871.82,349 ; CN1.16@1834.46,341.93 ccw(c1797.9,378.49) 1849.61,378.49 ccw(c1901.31,378.49) CN1.16@1864.75,341.93
PA15: CN1.18 R69.1 U1.63 | length 3447.7
  Top Layer w10: CN1.18@1949.61,326.79 1956.05,326.79 v1(2021,391.74) ; CN1.18@1949.61,338.21 ccw(c1949.61,381.33) 1980.1,350.83 ; CN1.18@1949.61,348.21 ccw(c1949.61,415.47) 1997.17,367.91 ; CN1.18@1949.61,358.21 ccw(c1949.61,449.61) v1@2014.24,384.98 ; CN1.18@1971.02,326.79 cw(c2007.17,326.79) 1981.61,352.35 ; CN1.18@1981.02,326.79 cw(c2041.32,326.79) 1998.68,369.42 ; v1@2016,391.74 cw(c2003.93,391.74) 2012.46,383.2 cw(c2021,374.67) v1@2021,386.74 ; v1(2042,1601) 2057,1601 2061.43,1605.43 U1.63@2148.68,1605.43 ; v1@2045.54,1597.46 cw(c2054.07,1588.93) 2054.07,1601 cw(c2054.07,1613.07) v1@2045.54,1604.54 ; v1(3558,1607) R69.1@3612,1607 ; v1@3561.54,1603.46 cw(c3570.07,1594.93) 3570.07,1607 cw(c3570.07,1619.07) v1@3561.54,1610.54 ; R69.1@3602.07,1600.79 ccw(c3587.08,1585.8) 3587.08,1607 ccw(c3587.08,1628.2) R69.1@3602.07,1613.21
  Bottom Layer w8: CN1.18@1949.61,306.79 CN1.18@1949.61,311.41
  Bottom Layer w10: v1@2016,391.74 ccw(c2003.93,391.74) 2012.46,400.27 ccw(c2021,408.81) v1@2021,396.74 ; v1(2021,391.74) 1966,446.74 1966,877 1966,1410.87 2006,1450.87 2006,1565 v1(2042,1601) 3502,1601 3508,1607 v1(3558,1607) ; v1@2037,1601 cw(c2024.93,1601) 2033.46,1592.46 cw(c2042,1583.93) v1@2042,1596 ; v1@2045.54,1597.46 cw(c2054.07,1588.93) 2054.07,1601 cw(c2054.07,1613.07) v1@2045.54,1604.54 ; v1@3554.46,1603.46 ccw(c3545.93,1594.93) 3545.93,1607 ccw(c3545.93,1619.07) v1@3554.46,1610.54
PB0: C13.1 CN2.25 U1.31 | length 4658.8
  Top Layer w10: CN2.25@2349.61,2606.79 2400,2657.18 ; CN2.25@2350.57,2628.18 ccw(c2352.57,2672.53) 2383.96,2641.14 ccw(c2415.35,2609.75) CN2.25@2371,2607.75 ; CN2.25@2351.02,2638.17 ccw(c2353.95,2703.22) 2400,2657.18 ; CN2.25@2380.99,2608.2 cw(c2446.04,2611.14) 2400,2657.18 ; U1.31@2699.86,1467.63 3032.37,1467.63 3235,1265 C13.1@3356,1265 3356,1290 ; C13.1@3347.16,1256.16 ccw(c3325.82,1234.82) 3325.82,1265 ccw(c3325.82,1295.18) C13.1@3347.16,1273.84 ; C13.1@3348.5,1275 ccw(c3337.25,1290) 3356,1290 ; C13.1@3363.5,1275 cw(c3374.75,1290) 3356,1290 ; 2400,2657.18 2400,2767 2461,2828 3441,2828 3997,2272 3997,1404 3850,1257 3527,1257 3479,1305 3371,1305 3356,1290
PB1: C14.1 CN2.27 U1.32 | length 4331.8
  Top Layer w10: CN2.27@2449.61,2606.79 2499.02,2656.2 ; CN2.27@2450.88,2628.17 ccw(c2453.4,2670.37) 2483.29,2640.47 ccw(c2513.18,2610.58) CN2.27@2470.99,2608.06 ; CN2.27@2451.48,2638.15 ccw(c2455.17,2700.05) 2499.02,2656.2 ; CN2.27@2480.97,2608.66 cw(c2542.87,2612.35) 2499.02,2656.2 ; U1.32@2699.86,1487.31 3055.69,1487.31 3196,1347 C14.1@3355,1347 3355,1372 ; C14.1@3346.16,1338.16 ccw(c3324.82,1316.82) 3324.82,1347 ccw(c3324.82,1377.18) C14.1@3346.16,1355.84 ; C14.1@3347.5,1357 ccw(c3336.25,1372) 3355,1372 ; C14.1@3362.5,1357 cw(c3373.75,1372) 3355,1372 ; 2499.02,2656.2 2499.02,2742.02 2567,2810 3408,2810 3952,2266 3952,1458 3851,1357 3527,1357 3487.97,1396.03 3379.03,1396.03 3355,1372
